(* Logix 5000 project; controller LinePLC1 vendor 1 type 14 code 154 rev 32.11; software revision 32.03; part 3 of 3 *)

ADD_ON_INSTRUCTION FC_Check8Bits   (* revision 1.0, vendor INTRALOX *)
// Check 8 Bits
VAR_INPUT
   b0 : BOOL;   // Input bit 0
   b1 : BOOL;   // Input bit 1
   b2 : BOOL;   // Input bit 2
   b3 : BOOL;   // Input bit 3
   b4 : BOOL;   // Input bit 4
   b5 : BOOL;   // Input bit 5
   b6 : BOOL;   // Input bit 6
   b7 : BOOL;   // Input bit 7
END_VAR
VAR_OUTPUT
   Check8Bits : BOOL;   // Check 8 bits
END_VAR
VAR
   Mem : INT; {access None}
END_VAR

ROUTINE Logic   (* structured text *)
// Check 8 Bits
   // Input bits into mem.
   Mem.0 := b0;
   Mem.1 := b1;
   Mem.2 := b2;
   Mem.3 := b3;
   Mem.4 := b4;
   Mem.5 := b5;
   Mem.6 := b6;
   Mem.7 := b7;
   
   // Make double sure to drop the first byte.
   Mem := Mem AND 16#00FF;
   
   // Check if multiple bits are set.
   IF (Mem AND Mem * -1) = Mem THEN
       Check8Bits := 1;
   ELSE
       Check8Bits := 0;
   END_IF;
   
END_ROUTINE
END_ADD_ON_INSTRUCTION

ADD_ON_INSTRUCTION FC_CheckMultipleBits   (* revision 1.0, vendor INTRALOX *)
// Check Multiple Bits
VAR_INPUT
   Input : INT;
END_VAR
VAR_OUTPUT
   CheckMultipleBits : BOOL; {access Read Only}
END_VAR

ROUTINE Logic   (* structured text *)
// Check Multiple Bits
   // Check if multiple bits are set.
   IF (Input AND Input * -1) = Input THEN
       CheckMultipleBits := 1;
   ELSE
       CheckMultipleBits := 0;
   END_IF;
   
END_ROUTINE
END_ADD_ON_INSTRUCTION

VAR_GLOBAL   (* controller tags *)
   DB_Constants : dt_Constant := (ParameterNr := 4, RecipeNr := 14); {constant, access None}
   DB_General_HMI : dt_General_HMI := (GeneralAlarmBtnCol := 1, AlarmBtnCol := 1); {access None}
   DB_Global : dt_Global; {access None}
   DB_M001_Comms : dt_ISC_CAM_Comm := (DataIn[0] := 23, DataIn[1] := 65535, DataIn[3] := 1, DataIn[4] := 3, DataIn[5] := 8, DataIn[6] := 616, DataIn[7] := 134, DataIn[10] := 60, DataIn[17] := 482, DataIn[19] := 9384, DataIn[21] := 690, DataIn[27] := 4487, DataIn[29] := 9, DataIn[31] := 4, DataIn[32] := 7737, DataIn[33] := 38, DataIn[34] := 616, DataIn[35] := 566, TempDataIn.W1 := 23, TempDataIn.W2 := 65535, TempDataIn.W4 := 1, TempDataIn.W5 := 3, TempDataIn.W6 := 8, TempDataIn.W7 := 616, TempDataIn.W8 := 134, TempDataIn.W11 := 60, TempDataIn.W18 := 482, TempDataIn.W20 := 9384, TempDataIn.W22 := 690, TempDataIn.W28 := 4487, TempDataIn.W30 := 9, TempDataIn.W32 := 4, TempDataIn.W33 := 7737, TempDataIn.W34 := 38, TempDataIn.W35 := 616, TempDataIn.W36 := 566, DataOut[0] := 3, DataOut[1] := 1, DataOut[7] := 1, TempDataOut.W1 := 3, TempDataOut.W2 := 1, TempDataOut.W8 := 1, CommHealthy := 1, CommStatus := 4, ConnectionStatus := 16384, Alarms.iCommsHealthy := 1, tempIn[0] := -581500805, tempIn[1] := 350281047, tempIn[2] := -290188064, tempIn[3] := -1950159180, tempIn[4] := 2984898, tempIn[5] := -515899347, tempIn[6] := 1077600576, tempIn[7] := 868410, tempIn[8] := 13, tempIn[47] := 1966080); {access None}
   DB_M001_HMI : dt_ISCCAM_HMI; {access None}
        .MaintenanceCounters.Counters[0]   // Belt run time - belt elongation.
        .MaintenanceCounters.Counters[1]   // Belt run time - belt contaminants.
        .MaintenanceCounters.Counters[2]   // Belt run time - wearstrip thickness.
        .MaintenanceCounters.Counters[3]   // Belt run time - helix rollers.
        .MaintenanceCounters.Counters[4]   // Belt run time - transfer rollers.
        .MaintenanceCounters.Counters[5]   // Belt run time - return rollers.
        .MaintenanceCounters.Counters[6]   // Belt run time - oil level drive motor.
        .MaintenanceCounters.Counters[7]   // Belt run time - cylinder movement, wear and contaminants, zone 0
        .MaintenanceCounters.Counters[8]   // Belt run time - cylinder movement, wear and contaminants, zone 1
        .MaintenanceCounters.Counters[9]   // Belt run time - cylinder movement, wear and contaminants, zone 2
        .MaintenanceCounters.Counters[10]   // Belt run time - pneumatic system check.
        .MaintenanceCounters.Counters[11]   // Spare
        .MaintenanceCounters.Counters[12]   // Spare
        .MaintenanceCounters.Counters[13]   // Spare
        .MaintenanceCounters.Counters[14]   // Spare
        .MaintenanceCounters.Counters[15]   // Spare
   DB_M001_ISC_CAM_Status : dt_ISC_CAM_Status := (Status.SystemReady := 1, Status.Error := 1, Status.FaultCode.FaultCode24 := 1, Status.FaultCode.FaultCode25 := 1, Status.FaultCode.FaultCode26 := 1, Status.FaultCode.FaultCode27 := 1, Status.FaultCode.FaultCode28 := 1, Status.FaultCode.FaultCode29 := 1, Status.FaultCode.FaultCode30 := 1, Status.FaultCode.FaultCode31 := 1, Status.FaultCode.FaultCode16 := 1, Status.FaultCode.FaultCode17 := 1, Status.FaultCode.FaultCode18 := 1, Status.FaultCode.FaultCode19 := 1, Status.FaultCode.FaultCode20 := 1, Status.FaultCode.FaultCode21 := 1, Status.FaultCode.FaultCode22 := 1, Status.FaultCode.FaultCode23 := 1, Status.Throughput := 3, Status.BeltSpeed := 8, Status.BeltAcceleration := 616, Status.IOstatus.IOStatus9 := 1, Status.IOstatus.IOStatus15 := 1, Status.UpTime := 60, Command.LifeBit := 1, Command.MotorRunning := 1, Command.AssignDestination := 1, Command.DES_Enable1 := 1, DataCollection.BeltRunTime := 482, DataCollection.BeltTravelDistance := 9384, DataCollection.ActivationCount_Zone_0 := 690, DataCollection.ProductCount := 4487, DataCollection.StartStops := 9, DataCollection.GapToSmallCount := 4, DataCollection.FaultCount := 7737, DataCollection.MaxBeltSpeed := 38, DataCollection.PeakAcceleration := 616, DataCollection.PeakDecceleration := 566); {access None}
   DB_M002_Comms : dt_ISC_CAM_Comm := (DataOut[0] := 7667715, DataOut[1] := 1, DataOut[7] := 1, TempDataOut.W1 := 7667715, TempDataOut.W2 := 1, TempDataOut.W8 := 1, CommStatus := 3, ConnectionStatus := 12288, IOConversion.Input := 1, tempIn[7] := -65518, tempIn[8] := 131072, tempIn[9] := 2359325, tempIn[10] := 131327, tempIn[12] := 140, tempIn[13] := 65581, tempIn[14] := 655360, tempIn[15] := 242417664, tempIn[16] := 1333133314, tempIn[17] := 268500992, tempIn[18] := 220528640, tempIn[20] := -1557135340, tempIn[21] := 16646144, tempIn[23] := 7673841, tempIn[24] := 255, tempIn[31] := -2147483618, tempIn[32] := -2147483616, tempIn[33] := -248024064, tempIn[34] := 8796, tempIn[35] := 2375874, tempIn[36] := 1, tempIn[37] := 32, tempIn[38] := 3, tempOut[7] := -65518, tempOut[8] := 131072, tempOut[9] := 2359325, tempOut[10] := 131327, tempOut[12] := 140, tempOut[13] := 65581, tempOut[14] := 655360, tempOut[15] := 242417664, tempOut[16] := 1333133314, tempOut[17] := 268500992, tempOut[18] := 220528640, tempOut[20] := -1557135340, tempOut[21] := 16646144, tempOut[23] := 7673841, tempOut[24] := 255, tempOut[31] := -2147483618, tempOut[32] := -2147483616, tempOut[33] := -248024064, tempOut[34] := 8796, tempOut[35] := 2375874, tempOut[36] := 1, tempOut[37] := 32, tempOut[38] := 3); {access None}
   DB_M002_HMI : dt_ISCCAM_HMI; {access None}
        .MaintenanceCounters.Counters[0]   // Belt run time - belt elongation.
        .MaintenanceCounters.Counters[1]   // Belt run time - belt contaminants.
        .MaintenanceCounters.Counters[2]   // Belt run time - wearstrip thickness.
        .MaintenanceCounters.Counters[3]   // Belt run time - helix rollers.
        .MaintenanceCounters.Counters[4]   // Belt run time - transfer rollers.
        .MaintenanceCounters.Counters[5]   // Belt run time - return rollers.
        .MaintenanceCounters.Counters[6]   // Belt run time - oil level drive motor.
        .MaintenanceCounters.Counters[7]   // Belt run time - cylinder movement, wear and contaminants, zone 0
        .MaintenanceCounters.Counters[8]   // Belt run time - cylinder movement, wear and contaminants, zone 1
        .MaintenanceCounters.Counters[9]   // Belt run time - cylinder movement, wear and contaminants, zone 2
        .MaintenanceCounters.Counters[10]   // Belt run time - pneumatic system check.
        .MaintenanceCounters.Counters[11]   // Spare
        .MaintenanceCounters.Counters[12]   // Spare
        .MaintenanceCounters.Counters[13]   // Spare
        .MaintenanceCounters.Counters[14]   // Spare
        .MaintenanceCounters.Counters[15]   // Spare
   DB_M002_ISC_CAM_Status : dt_ISC_CAM_Status := (Status.FaultCode.FaultCode8 := 1, Status.FaultCode.FaultCode9 := 1, Status.FaultCode.FaultCode10 := 1, Status.FaultCode.FaultCode11 := 1, Status.FaultCode.FaultCode12 := 1, Status.FaultCode.FaultCode13 := 1, Status.FaultCode.FaultCode14 := 1, Status.FaultCode.FaultCode15 := 1, Status.FaultCode.FaultCode0 := 1, Status.FaultCode.FaultCode1 := 1, Status.FaultCode.FaultCode2 := 1, Status.FaultCode.FaultCode3 := 1, Status.FaultCode.FaultCode4 := 1, Status.FaultCode.FaultCode5 := 1, Status.FaultCode.FaultCode6 := 1, Status.FaultCode.FaultCode7 := 1, Status.FaultCode.FaultCode24 := 1, Status.FaultCode.FaultCode25 := 1, Status.FaultCode.FaultCode26 := 1, Status.FaultCode.FaultCode27 := 1, Status.FaultCode.FaultCode28 := 1, Status.FaultCode.FaultCode29 := 1, Status.FaultCode.FaultCode30 := 1, Status.FaultCode.FaultCode31 := 1, Status.FaultCode.FaultCode16 := 1, Status.FaultCode.FaultCode17 := 1, Status.FaultCode.FaultCode18 := 1, Status.FaultCode.FaultCode19 := 1, Status.FaultCode.FaultCode20 := 1, Status.FaultCode.FaultCode21 := 1, Status.FaultCode.FaultCode22 := 1, Status.FaultCode.FaultCode23 := 1, Status.Alarms.CommsAlarm := 1, Status.Alarms.Fault8Alarm := 1, Status.Alarms.Fault9Alarm := 1, Status.Alarms.Fault10Alarm := 1, Status.Alarms.Fault11Alarm := 1, Status.Alarms.Fault12Alarm := 1, Status.Alarms.Fault13Alarm := 1, Status.Alarms.Fault14Alarm := 1, Status.Alarms.Fault15Alarm := 1, Status.Alarms.Fault0Alarm := 1, Status.Alarms.Fault1Alarm := 1, Status.Alarms.Fault2Alarm := 1, Status.Alarms.Fault3Alarm := 1, Status.Alarms.Fault4Alarm := 1, Status.Alarms.Fault5Alarm := 1, Status.Alarms.Fault6Alarm := 1, Status.Alarms.Fault7Alarm := 1, Command.LifeBit := 1, Command.MotorRunning := 1, Command.AssignDestination := 1, Command.DES_Enable1 := 1); {access None}
   DB_Maintenance_M001 : dt_ISC_CAM_Maintenance := (Maintenance[0].iCounter := 482, Maintenance[1].iCounter := 482, Maintenance[2].iCounter := 482, Maintenance[3].iCounter := 482, Maintenance[4].iCounter := 482, Maintenance[5].iCounter := 482, Maintenance[6].iCounter := 482, Maintenance[7].iCounter := 482, Maintenance[8].iCounter := 482, Maintenance[9].iCounter := 482, Maintenance[10].iCounter := 482); {access None}
        .Maintenance[14]   // Spare
        .Maintenance[12]   // Spare
        .Maintenance[13]   // Spare
        .Maintenance[15]   // Spare
        .Maintenance[0]   // Belt run time - belt elongation.
        .Maintenance[1]   // Belt run time - belt contaminants.
        .Maintenance[2]   // Belt run time - wearstrip thickness.
        .Maintenance[3]   // Belt run time - helix rollers.
        .Maintenance[4]   // Belt run time - transfer rollers.
        .Maintenance[5]   // Belt run time - return rollers.
        .Maintenance[6]   // Belt run time - oil level drive motor.
        .Maintenance[10]   // Belt run time - pneumatic system check.
        .Maintenance[11]   // Spare
        .Maintenance[7]   // Belt run time - cylinder movement, wear and contaminants, zone 0
        .Maintenance[8]   // Belt run time - cylinder movement, wear and contaminants, zone 1
        .Maintenance[9]   // Belt run time - cylinder movement, wear and contaminants, zone 2
   DB_Maintenance_M002 : dt_ISC_CAM_Maintenance := (Maintenance[0].iCounter := 16717809, Maintenance[1].iCounter := 16717809, Maintenance[2].iCounter := 16717809, Maintenance[3].iCounter := 16717809, Maintenance[4].iCounter := 16717809, Maintenance[5].iCounter := 16717809, Maintenance[6].iCounter := 16717809, Maintenance[7].iCounter := 16717809, Maintenance[8].iCounter := 16717809, Maintenance[9].iCounter := 16717809, Maintenance[10].iCounter := 16717809); {access None}
        .Maintenance[15]   // Spare
        .Maintenance[0]   // Belt run time - belt elongation.
        .Maintenance[1]   // Belt run time - belt contaminants.
        .Maintenance[2]   // Belt run time - wearstrip thickness.
        .Maintenance[3]   // Belt run time - helix rollers.
        .Maintenance[4]   // Belt run time - transfer rollers.
        .Maintenance[5]   // Belt run time - return rollers.
        .Maintenance[6]   // Belt run time - oil level drive motor.
        .Maintenance[10]   // Belt run time - pneumatic system check.
        .Maintenance[11]   // Spare
        .Maintenance[12]   // Spare
        .Maintenance[13]   // Spare
        .Maintenance[14]   // Spare
        .Maintenance[7]   // Belt run time - cylinder movement, wear and contaminants, zone 0
        .Maintenance[8]   // Belt run time - cylinder movement, wear and contaminants, zone 1
        .Maintenance[9]   // Belt run time - cylinder movement, wear and contaminants, zone 2
END_VAR

PROGRAM MainProgram   (* main routine MainRoutine *)
VAR
   FaultCount_M001 : DINT; {access None}
   FaultCount_M002 : DINT := 131071; {access None}
   fGO_Timer_00_M001 : FBD_TIMER := (PRE := 3000); {access None}
   fGO_Timer_00_M002 : FBD_TIMER := (TimerEnable := 1, PRE := 3000); {access None}
   fGO_Timer_01_M001 : FBD_TIMER := (PRE := 3000); {access None}
   fGO_Timer_01_M002 : FBD_TIMER := (PRE := 3000); {access None}
   i : SINT; {access None}
   iDB_Generl_Diagnostics : DINT; {access None}
END_VAR

ROUTINE General_Diagnostics   (* ladder *)
// General_Diagnostics
   // Add check routines for remote IO to be available / reacheable on th EIP network.
   // Done through msg instructions
   0: NOP();
END_ROUTINE

ROUTINE General_Faults   (* structured text *)
// General Faults
   // Collection of all fault bits.
   
   // General fault indicator.
   DB_General_HMI.GeneralFault := DB_General_HMI.GeneralFaultGroupBits <> 0;
   
END_ROUTINE

ROUTINE General_HMI   (* structured text *)
// General HMI
   // General HMI
   
   // Main alarm button color.
   // Fault color.
   IF DB_General_HMI.GeneralFault OR
       DB_M001_HMI.Fault OR
       DB_M002_HMI.Fault THEN
       DB_General_HMI.GeneralAlarmBtnCol := 1;
   // Maintenance color.
   ELSIF
       DB_M001_HMI.MaintenanceCounters.Counters[0].WarningBit OR DB_M001_HMI.MaintenanceCounters.Counters[1].WarningBit OR
       DB_M002_HMI.MaintenanceCounters.Counters[0].WarningBit OR DB_M002_HMI.MaintenanceCounters.Counters[1].WarningBit THEN
       DB_General_HMI.GeneralAlarmBtnCol := 3;
   // No color.
   ELSE
       DB_General_HMI.GeneralAlarmBtnCol := 0;
   END_IF;
   //;
   
   
   // Reset button.
   DB_General_HMI.GeneralResetBtnCmd := DB_General_HMI.GeneralResetBtnCmd; // Dummie
   //;
   
   
   // Alarm button color.
   // Fault color.
   IF DB_General_HMI.GeneralFault OR
       DB_M001_HMI.Fault OR
       DB_M002_HMI.Fault THEN
       DB_General_HMI.AlarmBtnCol := 1;
   // No color.
   ELSE
       DB_General_HMI.AlarmBtnCol := 0;
   END_IF;
   //;
   
   
   // Maintenance button color.
   // Fault color.
   IF DB_M001_HMI.MaintenanceCounters.Counters[0].WarningBit OR DB_M001_HMI.MaintenanceCounters.Counters[1].WarningBit OR
       DB_M002_HMI.MaintenanceCounters.Counters[0].WarningBit  OR DB_M002_HMI.MaintenanceCounters.Counters[1].WarningBit THEN
       DB_General_HMI.MaintenanceBtnCol := 3;
   // No color.
   ELSE
       DB_General_HMI.MaintenanceBtnCol := 0;
   END_IF;
   //;
   
   
END_ROUTINE

ROUTINE M001_Faults   (* structured text *)
   //Fault group 0, ISC device state errors.
   //Group reset
   If(DB_General_HMI.GeneralResetBtnCmd) Then
   	DB_M001_HMI.FaultBits.CommsAlarm := 0;
   	DB_M001_HMI.FaultBits.Fault0Alarm := 0;
   	DB_M001_HMI.FaultBits.Fault1Alarm := 0;
   	DB_M001_HMI.FaultBits.Fault2Alarm := 0;
   	DB_M001_HMI.FaultBits.Fault3Alarm := 0;
   	DB_M001_HMI.FaultBits.Fault4Alarm := 0;
   	DB_M001_HMI.FaultBits.Fault5Alarm := 0;
   	DB_M001_HMI.FaultBits.Fault6Alarm := 0;
   	DB_M001_HMI.FaultBits.Fault7Alarm := 0;
   	DB_M001_HMI.FaultBits.Fault8Alarm := 0;
   	DB_M001_HMI.FaultBits.Fault9Alarm := 0;
   	DB_M001_HMI.FaultBits.Fault10Alarm := 0;
   	DB_M001_HMI.FaultBits.Fault11Alarm := 0;
   	DB_M001_HMI.FaultBits.Fault12Alarm := 0;
   	DB_M001_HMI.FaultBits.Fault13Alarm := 0;
   	DB_M001_HMI.FaultBits.Fault14Alarm := 0;
   	DB_M001_HMI.FaultBits.Fault15Alarm := 0;
   end_if;
   
   
   //Lifebit error
   TONR(fGO_Timer_00_M001);
   fGO_Timer_00_M001.PRE := 3000;
   fGO_Timer_00_M001.TimerEnable := NOT DB_M001_ISC_CAM_Status.Status.LifeBit;
   
   TONR(fGO_Timer_01_M001);
   fGO_Timer_01_M001.PRE := 3000;
   fGO_Timer_01_M001.TimerEnable := DB_M001_ISC_CAM_Status.Status.LifeBit;
   
   
   If(NOT DB_M001_HMI.FaultBits.CommsAlarm  AND (fGO_Timer_00_M001.DN OR fGO_Timer_01_M001.DN)) then
   	DB_M001_HMI.FaultBits.CommsAlarm := 1;
   end_if;
   
   If(NOT DB_M001_HMI.FaultBits.Fault0Alarm  AND DB_M001_ISC_CAM_Status.Status.Alarms.Fault0Alarm) then
   	DB_M001_HMI.FaultBits.Fault0Alarm := 1;
   end_if;
   
   If(NOT DB_M001_HMI.FaultBits.Fault1Alarm  AND DB_M001_ISC_CAM_Status.Status.Alarms.Fault1Alarm) then
   	DB_M001_HMI.FaultBits.Fault1Alarm := 1;
   end_if;
   
   If(NOT DB_M001_HMI.FaultBits.Fault2Alarm  AND DB_M001_ISC_CAM_Status.Status.Alarms.Fault2Alarm) then
   	DB_M001_HMI.FaultBits.Fault2Alarm := 1;
   end_if;
   
   If(NOT DB_M001_HMI.FaultBits.Fault3Alarm  AND DB_M001_ISC_CAM_Status.Status.Alarms.Fault3Alarm) then
   	DB_M001_HMI.FaultBits.Fault3Alarm := 1;
   end_if;
   
   If(NOT DB_M001_HMI.FaultBits.Fault4Alarm  AND DB_M001_ISC_CAM_Status.Status.Alarms.Fault4Alarm) then
   	DB_M001_HMI.FaultBits.Fault4Alarm := 1;
   end_if;
   
   If(NOT DB_M001_HMI.FaultBits.Fault5Alarm  AND DB_M001_ISC_CAM_Status.Status.Alarms.Fault5Alarm) then
   	DB_M001_HMI.FaultBits.Fault5Alarm := 1;
   end_if;
   
   If(NOT DB_M001_HMI.FaultBits.Fault6Alarm  AND DB_M001_ISC_CAM_Status.Status.Alarms.Fault6Alarm) then
   	DB_M001_HMI.FaultBits.Fault6Alarm := 1;
   end_if;
   
   If(NOT DB_M001_HMI.FaultBits.Fault7Alarm  AND DB_M001_ISC_CAM_Status.Status.Alarms.Fault7Alarm) then
   	DB_M001_HMI.FaultBits.Fault7Alarm := 1;
   end_if;
   
   If(NOT DB_M001_HMI.FaultBits.Fault8Alarm  AND DB_M001_ISC_CAM_Status.Status.Alarms.Fault8Alarm) then
   	DB_M001_HMI.FaultBits.Fault8Alarm := 1;
   end_if;
   
   If(NOT DB_M001_HMI.FaultBits.Fault9Alarm  AND DB_M001_ISC_CAM_Status.Status.Alarms.Fault9Alarm) then
   	DB_M001_HMI.FaultBits.Fault9Alarm := 1;
   end_if;
   
   If(NOT DB_M001_HMI.FaultBits.Fault10Alarm  AND DB_M001_ISC_CAM_Status.Status.Alarms.Fault10Alarm) then
   	DB_M001_HMI.FaultBits.Fault10Alarm := 1;
   end_if;
   
   If(NOT DB_M001_HMI.FaultBits.Fault11Alarm  AND DB_M001_ISC_CAM_Status.Status.Alarms.Fault11Alarm) then
   	DB_M001_HMI.FaultBits.Fault11Alarm := 1;
   end_if;
   
   If(NOT DB_M001_HMI.FaultBits.Fault12Alarm  AND DB_M001_ISC_CAM_Status.Status.Alarms.Fault12Alarm) then
   	DB_M001_HMI.FaultBits.Fault12Alarm := 1;
   end_if;
   
   If(NOT DB_M001_HMI.FaultBits.Fault13Alarm  AND DB_M001_ISC_CAM_Status.Status.Alarms.Fault13Alarm) then
   	DB_M001_HMI.FaultBits.Fault13Alarm := 1;
   end_if;
   
   If(NOT DB_M001_HMI.FaultBits.Fault14Alarm  AND DB_M001_ISC_CAM_Status.Status.Alarms.Fault14Alarm) then
   	DB_M001_HMI.FaultBits.Fault14Alarm := 1;
   end_if;
   
   If(NOT DB_M001_HMI.FaultBits.Fault15Alarm  AND DB_M001_ISC_CAM_Status.Status.Alarms.Fault15Alarm) then
   	DB_M001_HMI.FaultBits.Fault15Alarm := 1;
   end_if;
   
   //Fault count
   COP(DB_M001_HMI.FaultBits, FaultCount_M001, 16);
   
   If(FaultCount_M001>0 AND NOT DB_M001_HMI.Fault) then
   	DB_M001_HMI.Fault := 1;
   elsif FaultCount_M001=0 AND DB_M001_HMI.Fault Then
   	DB_M001_HMI.Fault := 0;
   end_if;
END_ROUTINE

ROUTINE M001_Main   (* ladder *)
// M001 Main
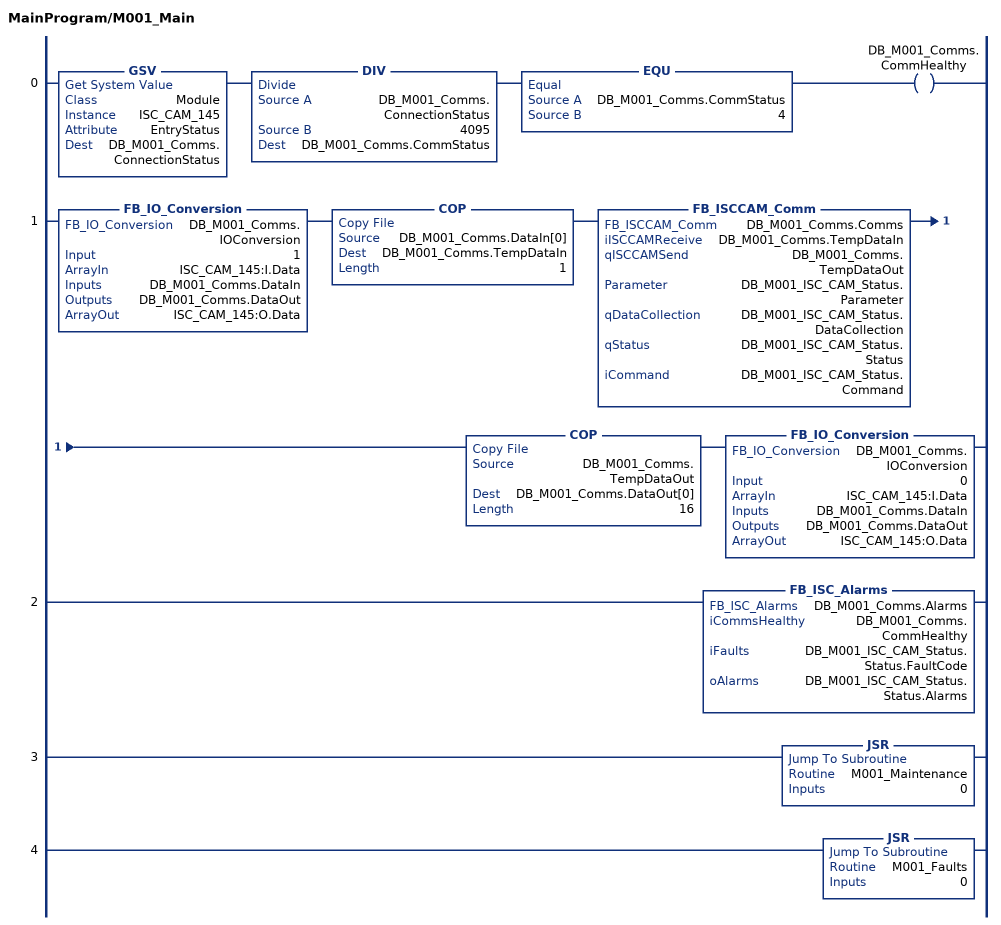
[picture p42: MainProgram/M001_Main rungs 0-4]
   0: GSV(Module,ISC_CAM_145,EntryStatus,DB_M001_Comms.ConnectionStatus)DIV(DB_M001_Comms.ConnectionStatus,4095,DB_M001_Comms.CommStatus)EQU(DB_M001_Comms.CommStatus,4)OTE(DB_M001_Comms.CommHealthy);
   1: FB_IO_Conversion(DB_M001_Comms.IOConversion,1,ISC_CAM_145:I.Data,DB_M001_Comms.DataIn,DB_M001_Comms.DataOut,ISC_CAM_145:O.Data)COP(DB_M001_Comms.DataIn[0],DB_M001_Comms.TempDataIn,1)FB_ISCCAM_Comm(DB_M001_Comms.Comms,DB_M001_Comms.TempDataIn,DB_M001_Comms.TempDataOut,DB_M001_ISC_CAM_Status.Parameter,DB_M001_ISC_CAM_Status.DataCollection,DB_M001_ISC_CAM_Status.Status,DB_M001_ISC_CAM_Status.Command)COP(DB_M001_Comms.TempDataOut,DB_M001_Comms.DataOut[0],16)FB_IO_Conversion(DB_M001_Comms.IOConversion,0,ISC_CAM_145:I.Data,DB_M001_Comms.DataIn,DB_M001_Comms.DataOut,ISC_CAM_145:O.Data);
   2: FB_ISC_Alarms(DB_M001_Comms.Alarms,DB_M001_Comms.CommHealthy,DB_M001_ISC_CAM_Status.Status.FaultCode,DB_M001_ISC_CAM_Status.Status.Alarms);
   3: JSR(M001_Maintenance,0);
   4: JSR(M001_Faults,0);
END_ROUTINE

ROUTINE M001_Maintenance   (* ladder *)
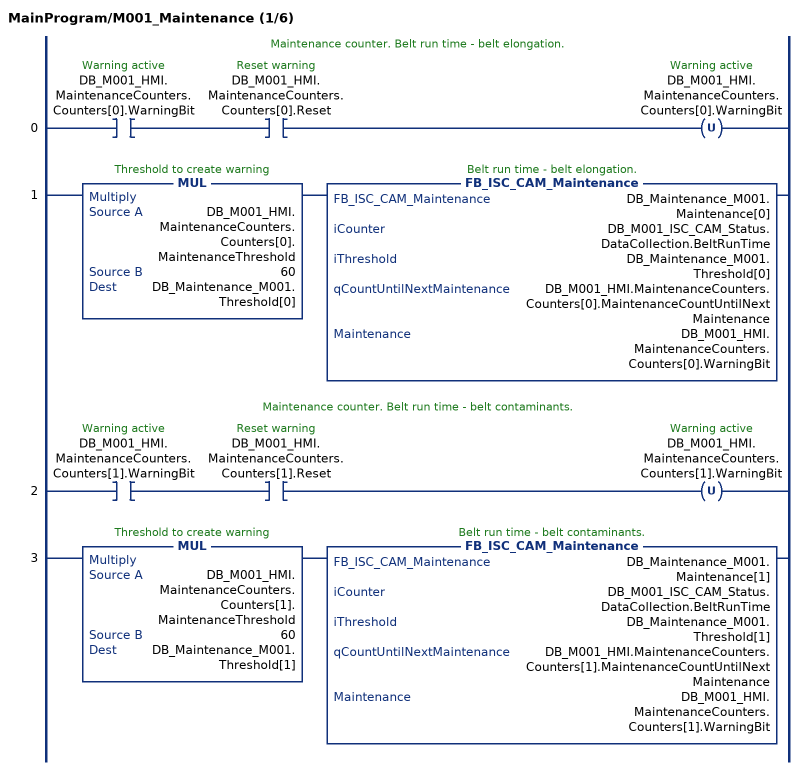
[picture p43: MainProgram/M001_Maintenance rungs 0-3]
   // Maintenance counter. Belt run time - belt elongation.
   0: XIC(DB_M001_HMI.MaintenanceCounters.Counters[0].WarningBit)XIC(DB_M001_HMI.MaintenanceCounters.Counters[0].Reset)OTU(DB_M001_HMI.MaintenanceCounters.Counters[0].WarningBit);
   1: MUL(DB_M001_HMI.MaintenanceCounters.Counters[0].MaintenanceThreshold,60,DB_Maintenance_M001.Threshold[0])FB_ISC_CAM_Maintenance(DB_Maintenance_M001.Maintenance[0],DB_M001_ISC_CAM_Status.DataCollection.BeltRunTime,DB_Maintenance_M001.Threshold[0],DB_M001_HMI.MaintenanceCounters.Counters[0].MaintenanceCountUntilNextMaintenance,DB_M001_HMI.MaintenanceCounters.Counters[0].WarningBit);
   // Maintenance counter. Belt run time - belt contaminants.
   2: XIC(DB_M001_HMI.MaintenanceCounters.Counters[1].WarningBit)XIC(DB_M001_HMI.MaintenanceCounters.Counters[1].Reset)OTU(DB_M001_HMI.MaintenanceCounters.Counters[1].WarningBit);
   3: MUL(DB_M001_HMI.MaintenanceCounters.Counters[1].MaintenanceThreshold,60,DB_Maintenance_M001.Threshold[1])FB_ISC_CAM_Maintenance(DB_Maintenance_M001.Maintenance[1],DB_M001_ISC_CAM_Status.DataCollection.BeltRunTime,DB_Maintenance_M001.Threshold[1],DB_M001_HMI.MaintenanceCounters.Counters[1].MaintenanceCountUntilNextMaintenance,DB_M001_HMI.MaintenanceCounters.Counters[1].WarningBit);
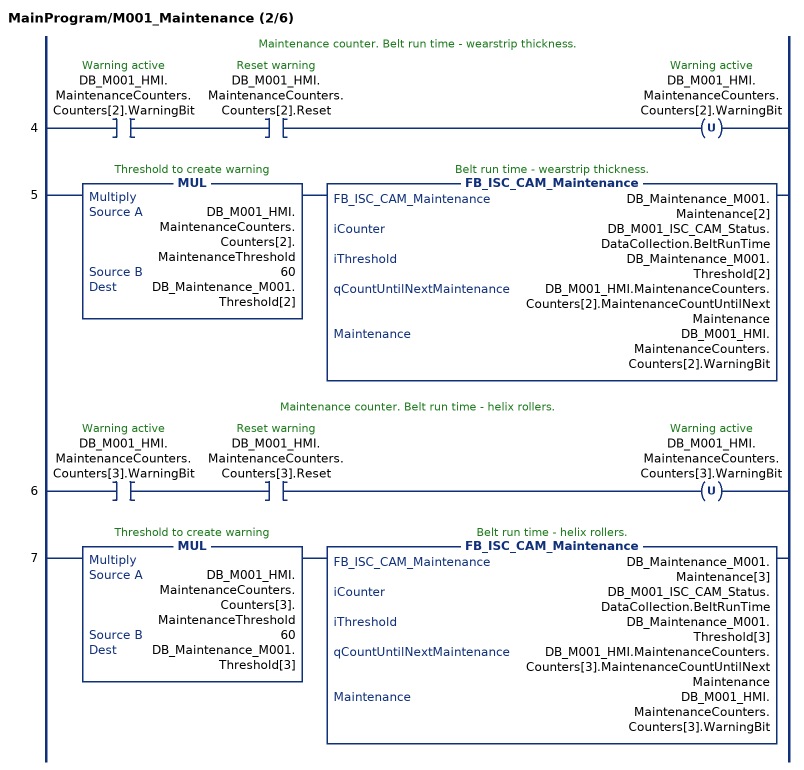
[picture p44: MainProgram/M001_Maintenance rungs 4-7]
   // Maintenance counter. Belt run time - wearstrip thickness.
   4: XIC(DB_M001_HMI.MaintenanceCounters.Counters[2].WarningBit)XIC(DB_M001_HMI.MaintenanceCounters.Counters[2].Reset)OTU(DB_M001_HMI.MaintenanceCounters.Counters[2].WarningBit);
   5: MUL(DB_M001_HMI.MaintenanceCounters.Counters[2].MaintenanceThreshold,60,DB_Maintenance_M001.Threshold[2])FB_ISC_CAM_Maintenance(DB_Maintenance_M001.Maintenance[2],DB_M001_ISC_CAM_Status.DataCollection.BeltRunTime,DB_Maintenance_M001.Threshold[2],DB_M001_HMI.MaintenanceCounters.Counters[2].MaintenanceCountUntilNextMaintenance,DB_M001_HMI.MaintenanceCounters.Counters[2].WarningBit);
   // Maintenance counter. Belt run time - helix rollers.
   6: XIC(DB_M001_HMI.MaintenanceCounters.Counters[3].WarningBit)XIC(DB_M001_HMI.MaintenanceCounters.Counters[3].Reset)OTU(DB_M001_HMI.MaintenanceCounters.Counters[3].WarningBit);
   7: MUL(DB_M001_HMI.MaintenanceCounters.Counters[3].MaintenanceThreshold,60,DB_Maintenance_M001.Threshold[3])FB_ISC_CAM_Maintenance(DB_Maintenance_M001.Maintenance[3],DB_M001_ISC_CAM_Status.DataCollection.BeltRunTime,DB_Maintenance_M001.Threshold[3],DB_M001_HMI.MaintenanceCounters.Counters[3].MaintenanceCountUntilNextMaintenance,DB_M001_HMI.MaintenanceCounters.Counters[3].WarningBit);
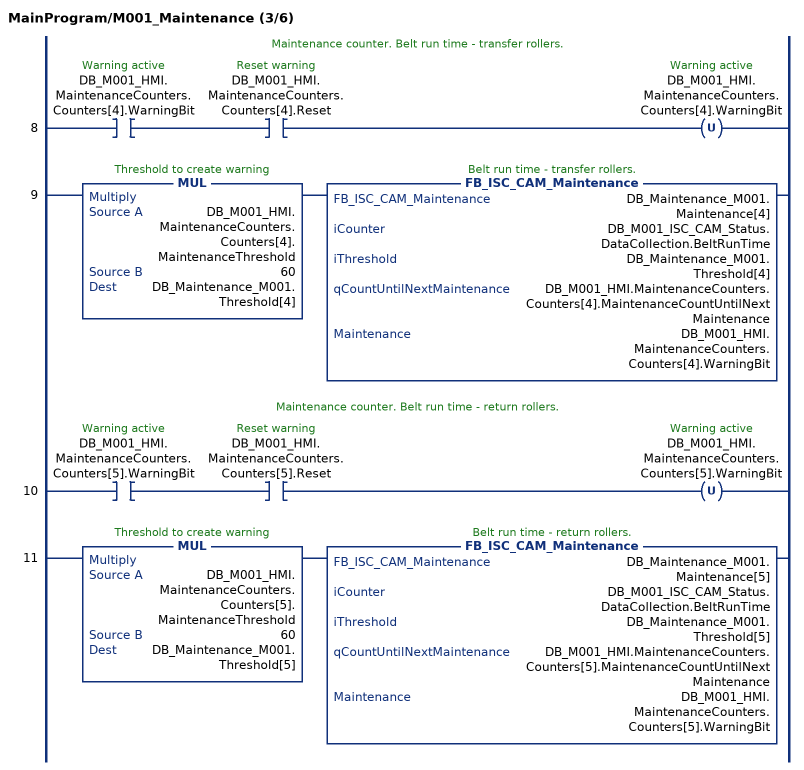
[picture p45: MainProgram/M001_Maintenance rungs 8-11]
   // Maintenance counter. Belt run time - transfer rollers.
   8: XIC(DB_M001_HMI.MaintenanceCounters.Counters[4].WarningBit)XIC(DB_M001_HMI.MaintenanceCounters.Counters[4].Reset)OTU(DB_M001_HMI.MaintenanceCounters.Counters[4].WarningBit);
   9: MUL(DB_M001_HMI.MaintenanceCounters.Counters[4].MaintenanceThreshold,60,DB_Maintenance_M001.Threshold[4])FB_ISC_CAM_Maintenance(DB_Maintenance_M001.Maintenance[4],DB_M001_ISC_CAM_Status.DataCollection.BeltRunTime,DB_Maintenance_M001.Threshold[4],DB_M001_HMI.MaintenanceCounters.Counters[4].MaintenanceCountUntilNextMaintenance,DB_M001_HMI.MaintenanceCounters.Counters[4].WarningBit);
   // Maintenance counter. Belt run time - return rollers.
   10: XIC(DB_M001_HMI.MaintenanceCounters.Counters[5].WarningBit)XIC(DB_M001_HMI.MaintenanceCounters.Counters[5].Reset)OTU(DB_M001_HMI.MaintenanceCounters.Counters[5].WarningBit);
   11: MUL(DB_M001_HMI.MaintenanceCounters.Counters[5].MaintenanceThreshold,60,DB_Maintenance_M001.Threshold[5])FB_ISC_CAM_Maintenance(DB_Maintenance_M001.Maintenance[5],DB_M001_ISC_CAM_Status.DataCollection.BeltRunTime,DB_Maintenance_M001.Threshold[5],DB_M001_HMI.MaintenanceCounters.Counters[5].MaintenanceCountUntilNextMaintenance,DB_M001_HMI.MaintenanceCounters.Counters[5].WarningBit);
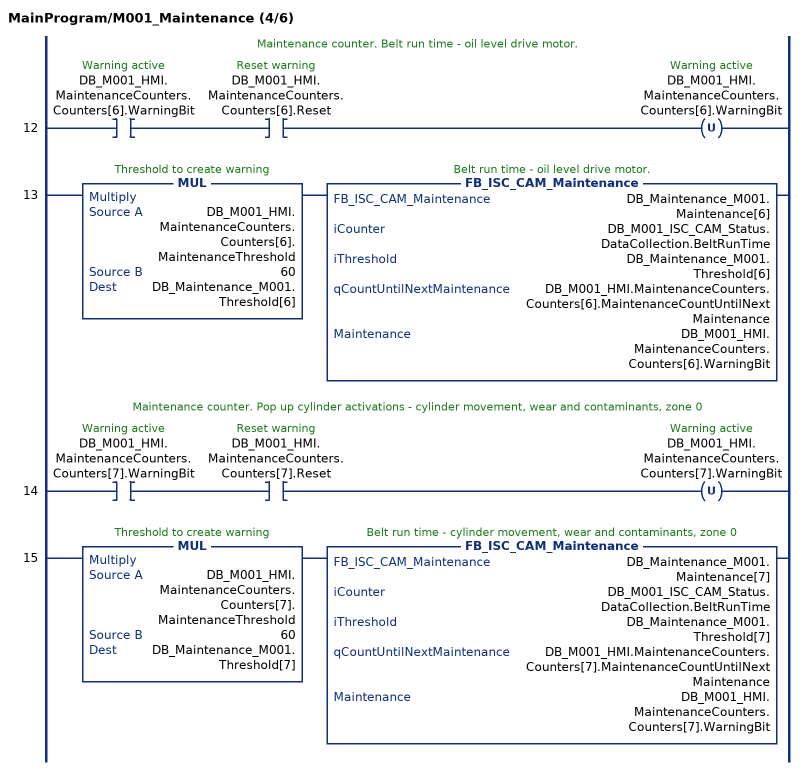
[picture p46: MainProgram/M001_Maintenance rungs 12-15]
   // Maintenance counter. Belt run time - oil level drive motor.
   12: XIC(DB_M001_HMI.MaintenanceCounters.Counters[6].WarningBit)XIC(DB_M001_HMI.MaintenanceCounters.Counters[6].Reset)OTU(DB_M001_HMI.MaintenanceCounters.Counters[6].WarningBit);
   13: MUL(DB_M001_HMI.MaintenanceCounters.Counters[6].MaintenanceThreshold,60,DB_Maintenance_M001.Threshold[6])FB_ISC_CAM_Maintenance(DB_Maintenance_M001.Maintenance[6],DB_M001_ISC_CAM_Status.DataCollection.BeltRunTime,DB_Maintenance_M001.Threshold[6],DB_M001_HMI.MaintenanceCounters.Counters[6].MaintenanceCountUntilNextMaintenance,DB_M001_HMI.MaintenanceCounters.Counters[6].WarningBit);
   // Maintenance counter. Pop up cylinder activations - cylinder movement, wear and contaminants, zone 0
   14: XIC(DB_M001_HMI.MaintenanceCounters.Counters[7].WarningBit)XIC(DB_M001_HMI.MaintenanceCounters.Counters[7].Reset)OTU(DB_M001_HMI.MaintenanceCounters.Counters[7].WarningBit);
   15: MUL(DB_M001_HMI.MaintenanceCounters.Counters[7].MaintenanceThreshold,60,DB_Maintenance_M001.Threshold[7])FB_ISC_CAM_Maintenance(DB_Maintenance_M001.Maintenance[7],DB_M001_ISC_CAM_Status.DataCollection.BeltRunTime,DB_Maintenance_M001.Threshold[7],DB_M001_HMI.MaintenanceCounters.Counters[7].MaintenanceCountUntilNextMaintenance,DB_M001_HMI.MaintenanceCounters.Counters[7].WarningBit);
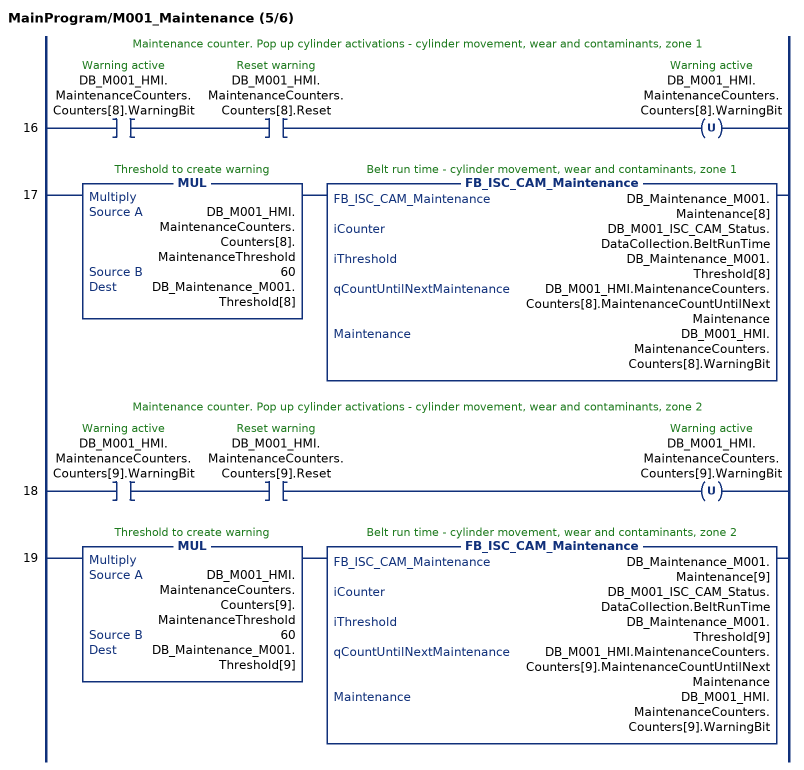
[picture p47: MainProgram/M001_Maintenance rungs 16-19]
   // Maintenance counter. Pop up cylinder activations - cylinder movement, wear and contaminants, zone 1
   16: XIC(DB_M001_HMI.MaintenanceCounters.Counters[8].WarningBit)XIC(DB_M001_HMI.MaintenanceCounters.Counters[8].Reset)OTU(DB_M001_HMI.MaintenanceCounters.Counters[8].WarningBit);
   17: MUL(DB_M001_HMI.MaintenanceCounters.Counters[8].MaintenanceThreshold,60,DB_Maintenance_M001.Threshold[8])FB_ISC_CAM_Maintenance(DB_Maintenance_M001.Maintenance[8],DB_M001_ISC_CAM_Status.DataCollection.BeltRunTime,DB_Maintenance_M001.Threshold[8],DB_M001_HMI.MaintenanceCounters.Counters[8].MaintenanceCountUntilNextMaintenance,DB_M001_HMI.MaintenanceCounters.Counters[8].WarningBit);
   // Maintenance counter. Pop up cylinder activations - cylinder movement, wear and contaminants, zone 2
   18: XIC(DB_M001_HMI.MaintenanceCounters.Counters[9].WarningBit)XIC(DB_M001_HMI.MaintenanceCounters.Counters[9].Reset)OTU(DB_M001_HMI.MaintenanceCounters.Counters[9].WarningBit);
   19: MUL(DB_M001_HMI.MaintenanceCounters.Counters[9].MaintenanceThreshold,60,DB_Maintenance_M001.Threshold[9])FB_ISC_CAM_Maintenance(DB_Maintenance_M001.Maintenance[9],DB_M001_ISC_CAM_Status.DataCollection.BeltRunTime,DB_Maintenance_M001.Threshold[9],DB_M001_HMI.MaintenanceCounters.Counters[9].MaintenanceCountUntilNextMaintenance,DB_M001_HMI.MaintenanceCounters.Counters[9].WarningBit);
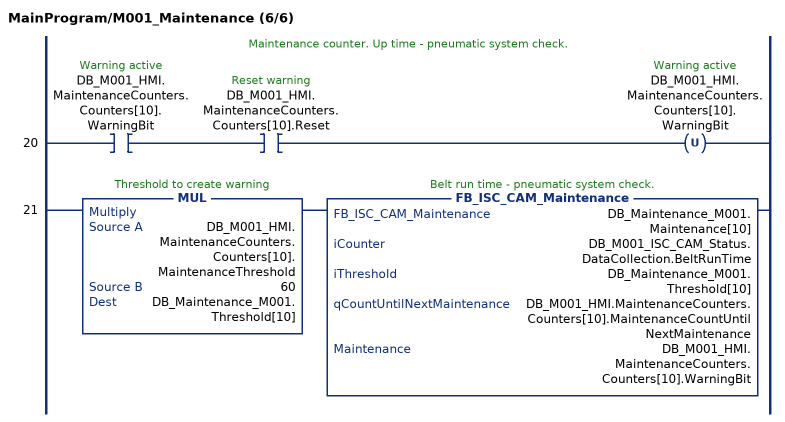
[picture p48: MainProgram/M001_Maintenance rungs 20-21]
   // Maintenance counter. Up time - pneumatic system check.
   20: XIC(DB_M001_HMI.MaintenanceCounters.Counters[10].WarningBit)XIC(DB_M001_HMI.MaintenanceCounters.Counters[10].Reset)OTU(DB_M001_HMI.MaintenanceCounters.Counters[10].WarningBit);
   21: MUL(DB_M001_HMI.MaintenanceCounters.Counters[10].MaintenanceThreshold,60,DB_Maintenance_M001.Threshold[10])FB_ISC_CAM_Maintenance(DB_Maintenance_M001.Maintenance[10],DB_M001_ISC_CAM_Status.DataCollection.BeltRunTime,DB_Maintenance_M001.Threshold[10],DB_M001_HMI.MaintenanceCounters.Counters[10].MaintenanceCountUntilNextMaintenance,DB_M001_HMI.MaintenanceCounters.Counters[10].WarningBit);
END_ROUTINE

ROUTINE M002_Faults   (* structured text *)
   //Fault group 0, ISC device state errors.
   //Group reset
   If(DB_General_HMI.GeneralResetBtnCmd) Then
   	DB_M002_HMI.FaultBits.CommsAlarm := 0;
   	DB_M002_HMI.FaultBits.Fault0Alarm := 0;
   	DB_M002_HMI.FaultBits.Fault1Alarm := 0;
   	DB_M002_HMI.FaultBits.Fault2Alarm := 0;
   	DB_M002_HMI.FaultBits.Fault3Alarm := 0;
   	DB_M002_HMI.FaultBits.Fault4Alarm := 0;
   	DB_M002_HMI.FaultBits.Fault5Alarm := 0;
   	DB_M002_HMI.FaultBits.Fault6Alarm := 0;
   	DB_M002_HMI.FaultBits.Fault7Alarm := 0;
   	DB_M002_HMI.FaultBits.Fault8Alarm := 0;
   	DB_M002_HMI.FaultBits.Fault9Alarm := 0;
   	DB_M002_HMI.FaultBits.Fault10Alarm := 0;
   	DB_M002_HMI.FaultBits.Fault11Alarm := 0;
   	DB_M002_HMI.FaultBits.Fault12Alarm := 0;
   	DB_M002_HMI.FaultBits.Fault13Alarm := 0;
   	DB_M002_HMI.FaultBits.Fault14Alarm := 0;
   	DB_M002_HMI.FaultBits.Fault15Alarm := 0;
   end_if;
   
   
   //Lifebit error
   TONR(fGO_Timer_00_M002);
   fGO_Timer_00_M002.PRE := 3000;
   fGO_Timer_00_M002.TimerEnable := NOT DB_M002_ISC_CAM_Status.Status.LifeBit;
   
   TONR(fGO_Timer_01_M002);
   fGO_Timer_01_M002.PRE := 3000;
   fGO_Timer_01_M002.TimerEnable := DB_M002_ISC_CAM_Status.Status.LifeBit;
   
   
   If(NOT DB_M002_HMI.FaultBits.CommsAlarm  AND (fGO_Timer_00_M002.DN OR fGO_Timer_01_M002.DN)) then
   	DB_M002_HMI.FaultBits.CommsAlarm := 1;
   end_if;
   
   If(NOT DB_M002_HMI.FaultBits.Fault0Alarm  AND DB_M002_ISC_CAM_Status.Status.Alarms.Fault0Alarm) then
   	DB_M002_HMI.FaultBits.Fault0Alarm := 1;
   end_if;
   
   If(NOT DB_M002_HMI.FaultBits.Fault1Alarm  AND DB_M002_ISC_CAM_Status.Status.Alarms.Fault1Alarm) then
   	DB_M002_HMI.FaultBits.Fault1Alarm := 1;
   end_if;
   
   If(NOT DB_M002_HMI.FaultBits.Fault2Alarm  AND DB_M002_ISC_CAM_Status.Status.Alarms.Fault2Alarm) then
   	DB_M002_HMI.FaultBits.Fault2Alarm := 1;
   end_if;
   
   If(NOT DB_M002_HMI.FaultBits.Fault3Alarm  AND DB_M002_ISC_CAM_Status.Status.Alarms.Fault3Alarm) then
   	DB_M002_HMI.FaultBits.Fault3Alarm := 1;
   end_if;
   
   If(NOT DB_M002_HMI.FaultBits.Fault4Alarm  AND DB_M002_ISC_CAM_Status.Status.Alarms.Fault4Alarm) then
   	DB_M002_HMI.FaultBits.Fault4Alarm := 1;
   end_if;
   
   If(NOT DB_M002_HMI.FaultBits.Fault5Alarm  AND DB_M002_ISC_CAM_Status.Status.Alarms.Fault5Alarm) then
   	DB_M002_HMI.FaultBits.Fault5Alarm := 1;
   end_if;
   
   If(NOT DB_M002_HMI.FaultBits.Fault6Alarm  AND DB_M002_ISC_CAM_Status.Status.Alarms.Fault6Alarm) then
   	DB_M002_HMI.FaultBits.Fault6Alarm := 1;
   end_if;
   
   If(NOT DB_M002_HMI.FaultBits.Fault7Alarm  AND DB_M002_ISC_CAM_Status.Status.Alarms.Fault7Alarm) then
   	DB_M002_HMI.FaultBits.Fault7Alarm := 1;
   end_if;
   
   If(NOT DB_M002_HMI.FaultBits.Fault8Alarm  AND DB_M002_ISC_CAM_Status.Status.Alarms.Fault8Alarm) then
   	DB_M002_HMI.FaultBits.Fault8Alarm := 1;
   end_if;
   
   If(NOT DB_M002_HMI.FaultBits.Fault9Alarm  AND DB_M002_ISC_CAM_Status.Status.Alarms.Fault9Alarm) then
   	DB_M002_HMI.FaultBits.Fault9Alarm := 1;
   end_if;
   
   If(NOT DB_M002_HMI.FaultBits.Fault10Alarm  AND DB_M002_ISC_CAM_Status.Status.Alarms.Fault10Alarm) then
   	DB_M002_HMI.FaultBits.Fault10Alarm := 1;
   end_if;
   
   If(NOT DB_M002_HMI.FaultBits.Fault11Alarm  AND DB_M002_ISC_CAM_Status.Status.Alarms.Fault11Alarm) then
   	DB_M002_HMI.FaultBits.Fault11Alarm := 1;
   end_if;
   
   If(NOT DB_M002_HMI.FaultBits.Fault12Alarm  AND DB_M002_ISC_CAM_Status.Status.Alarms.Fault12Alarm) then
   	DB_M002_HMI.FaultBits.Fault12Alarm := 1;
   end_if;
   
   If(NOT DB_M002_HMI.FaultBits.Fault13Alarm  AND DB_M002_ISC_CAM_Status.Status.Alarms.Fault13Alarm) then
   	DB_M002_HMI.FaultBits.Fault13Alarm := 1;
   end_if;
   
   If(NOT DB_M002_HMI.FaultBits.Fault14Alarm  AND DB_M002_ISC_CAM_Status.Status.Alarms.Fault14Alarm) then
   	DB_M002_HMI.FaultBits.Fault14Alarm := 1;
   end_if;
   
   If(NOT DB_M002_HMI.FaultBits.Fault15Alarm  AND DB_M002_ISC_CAM_Status.Status.Alarms.Fault15Alarm) then
   	DB_M002_HMI.FaultBits.Fault15Alarm := 1;
   end_if;
   
   //Fault count
   COP(DB_M002_HMI.FaultBits, FaultCount_M002, 16);
   
   If(FaultCount_M002>0 AND NOT DB_M002_HMI.Fault) then
   	DB_M002_HMI.Fault := 1;
   elsif FaultCount_M002=0 AND DB_M002_HMI.Fault Then
   	DB_M002_HMI.Fault := 0;
   end_if;
END_ROUTINE

ROUTINE M002_Main   (* ladder *)
// M002 Main
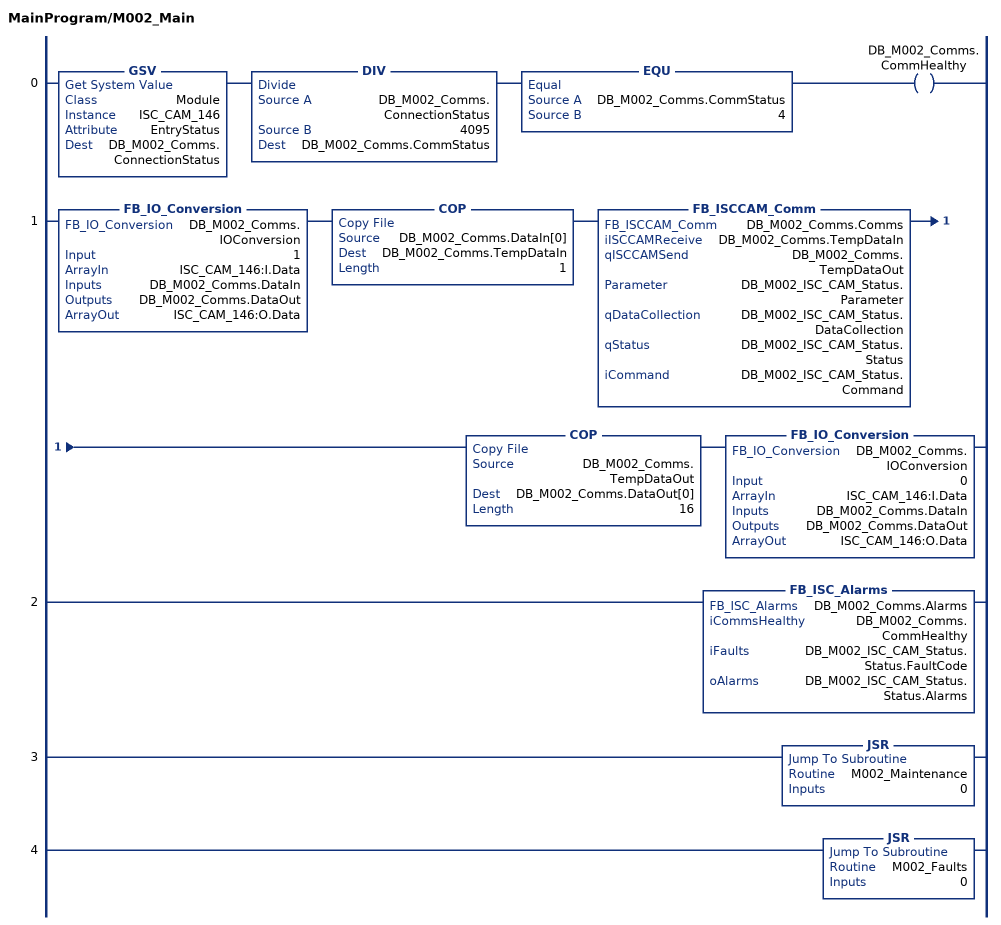
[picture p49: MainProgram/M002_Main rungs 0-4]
   0: GSV(Module,ISC_CAM_146,EntryStatus,DB_M002_Comms.ConnectionStatus)DIV(DB_M002_Comms.ConnectionStatus,4095,DB_M002_Comms.CommStatus)EQU(DB_M002_Comms.CommStatus,4)OTE(DB_M002_Comms.CommHealthy);
   1: FB_IO_Conversion(DB_M002_Comms.IOConversion,1,ISC_CAM_146:I.Data,DB_M002_Comms.DataIn,DB_M002_Comms.DataOut,ISC_CAM_146:O.Data)COP(DB_M002_Comms.DataIn[0],DB_M002_Comms.TempDataIn,1)FB_ISCCAM_Comm(DB_M002_Comms.Comms,DB_M002_Comms.TempDataIn,DB_M002_Comms.TempDataOut,DB_M002_ISC_CAM_Status.Parameter,DB_M002_ISC_CAM_Status.DataCollection,DB_M002_ISC_CAM_Status.Status,DB_M002_ISC_CAM_Status.Command)COP(DB_M002_Comms.TempDataOut,DB_M002_Comms.DataOut[0],16)FB_IO_Conversion(DB_M002_Comms.IOConversion,0,ISC_CAM_146:I.Data,DB_M002_Comms.DataIn,DB_M002_Comms.DataOut,ISC_CAM_146:O.Data);
   2: FB_ISC_Alarms(DB_M002_Comms.Alarms,DB_M002_Comms.CommHealthy,DB_M002_ISC_CAM_Status.Status.FaultCode,DB_M002_ISC_CAM_Status.Status.Alarms);
   3: JSR(M002_Maintenance,0);
   4: JSR(M002_Faults,0);
END_ROUTINE

ROUTINE M002_Maintenance   (* ladder *)
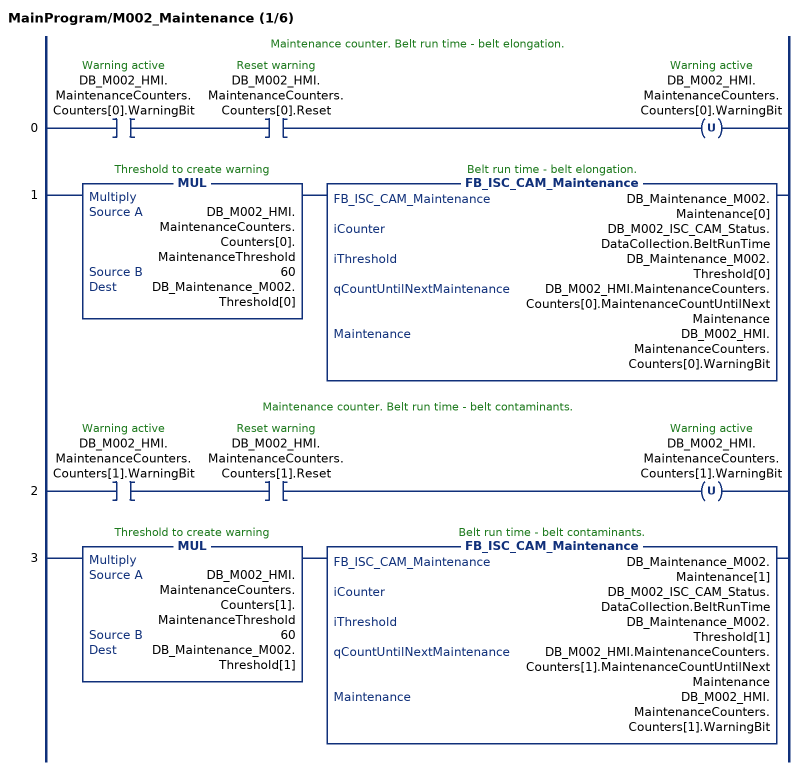
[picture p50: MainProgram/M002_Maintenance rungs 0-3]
   // Maintenance counter. Belt run time - belt elongation.
   0: XIC(DB_M002_HMI.MaintenanceCounters.Counters[0].WarningBit)XIC(DB_M002_HMI.MaintenanceCounters.Counters[0].Reset)OTU(DB_M002_HMI.MaintenanceCounters.Counters[0].WarningBit);
   1: MUL(DB_M002_HMI.MaintenanceCounters.Counters[0].MaintenanceThreshold,60,DB_Maintenance_M002.Threshold[0])FB_ISC_CAM_Maintenance(DB_Maintenance_M002.Maintenance[0],DB_M002_ISC_CAM_Status.DataCollection.BeltRunTime,DB_Maintenance_M002.Threshold[0],DB_M002_HMI.MaintenanceCounters.Counters[0].MaintenanceCountUntilNextMaintenance,DB_M002_HMI.MaintenanceCounters.Counters[0].WarningBit);
   // Maintenance counter. Belt run time - belt contaminants.
   2: XIC(DB_M002_HMI.MaintenanceCounters.Counters[1].WarningBit)XIC(DB_M002_HMI.MaintenanceCounters.Counters[1].Reset)OTU(DB_M002_HMI.MaintenanceCounters.Counters[1].WarningBit);
   3: MUL(DB_M002_HMI.MaintenanceCounters.Counters[1].MaintenanceThreshold,60,DB_Maintenance_M002.Threshold[1])FB_ISC_CAM_Maintenance(DB_Maintenance_M002.Maintenance[1],DB_M002_ISC_CAM_Status.DataCollection.BeltRunTime,DB_Maintenance_M002.Threshold[1],DB_M002_HMI.MaintenanceCounters.Counters[1].MaintenanceCountUntilNextMaintenance,DB_M002_HMI.MaintenanceCounters.Counters[1].WarningBit);
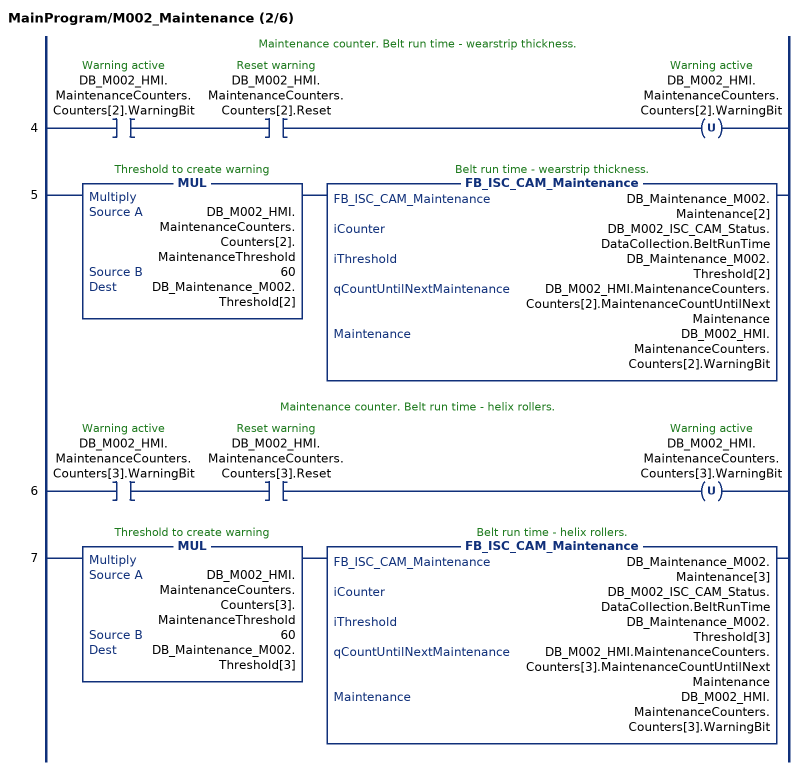
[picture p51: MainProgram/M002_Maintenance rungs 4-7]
   // Maintenance counter. Belt run time - wearstrip thickness.
   4: XIC(DB_M002_HMI.MaintenanceCounters.Counters[2].WarningBit)XIC(DB_M002_HMI.MaintenanceCounters.Counters[2].Reset)OTU(DB_M002_HMI.MaintenanceCounters.Counters[2].WarningBit);
   5: MUL(DB_M002_HMI.MaintenanceCounters.Counters[2].MaintenanceThreshold,60,DB_Maintenance_M002.Threshold[2])FB_ISC_CAM_Maintenance(DB_Maintenance_M002.Maintenance[2],DB_M002_ISC_CAM_Status.DataCollection.BeltRunTime,DB_Maintenance_M002.Threshold[2],DB_M002_HMI.MaintenanceCounters.Counters[2].MaintenanceCountUntilNextMaintenance,DB_M002_HMI.MaintenanceCounters.Counters[2].WarningBit);
   // Maintenance counter. Belt run time - helix rollers.
   6: XIC(DB_M002_HMI.MaintenanceCounters.Counters[3].WarningBit)XIC(DB_M002_HMI.MaintenanceCounters.Counters[3].Reset)OTU(DB_M002_HMI.MaintenanceCounters.Counters[3].WarningBit);
   7: MUL(DB_M002_HMI.MaintenanceCounters.Counters[3].MaintenanceThreshold,60,DB_Maintenance_M002.Threshold[3])FB_ISC_CAM_Maintenance(DB_Maintenance_M002.Maintenance[3],DB_M002_ISC_CAM_Status.DataCollection.BeltRunTime,DB_Maintenance_M002.Threshold[3],DB_M002_HMI.MaintenanceCounters.Counters[3].MaintenanceCountUntilNextMaintenance,DB_M002_HMI.MaintenanceCounters.Counters[3].WarningBit);
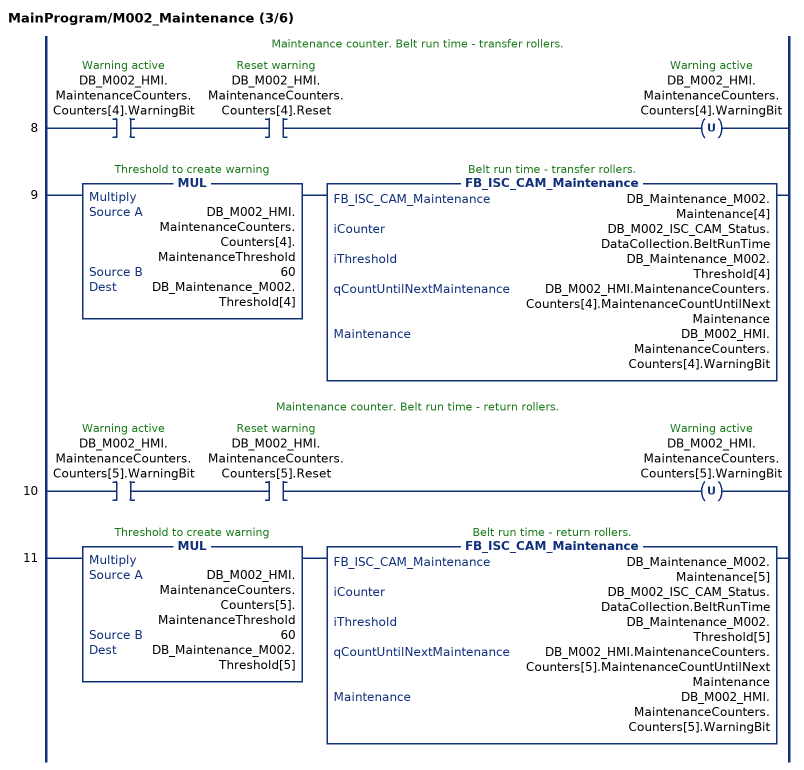
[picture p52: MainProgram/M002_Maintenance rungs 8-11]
   // Maintenance counter. Belt run time - transfer rollers.
   8: XIC(DB_M002_HMI.MaintenanceCounters.Counters[4].WarningBit)XIC(DB_M002_HMI.MaintenanceCounters.Counters[4].Reset)OTU(DB_M002_HMI.MaintenanceCounters.Counters[4].WarningBit);
   9: MUL(DB_M002_HMI.MaintenanceCounters.Counters[4].MaintenanceThreshold,60,DB_Maintenance_M002.Threshold[4])FB_ISC_CAM_Maintenance(DB_Maintenance_M002.Maintenance[4],DB_M002_ISC_CAM_Status.DataCollection.BeltRunTime,DB_Maintenance_M002.Threshold[4],DB_M002_HMI.MaintenanceCounters.Counters[4].MaintenanceCountUntilNextMaintenance,DB_M002_HMI.MaintenanceCounters.Counters[4].WarningBit);
   // Maintenance counter. Belt run time - return rollers.
   10: XIC(DB_M002_HMI.MaintenanceCounters.Counters[5].WarningBit)XIC(DB_M002_HMI.MaintenanceCounters.Counters[5].Reset)OTU(DB_M002_HMI.MaintenanceCounters.Counters[5].WarningBit);
   11: MUL(DB_M002_HMI.MaintenanceCounters.Counters[5].MaintenanceThreshold,60,DB_Maintenance_M002.Threshold[5])FB_ISC_CAM_Maintenance(DB_Maintenance_M002.Maintenance[5],DB_M002_ISC_CAM_Status.DataCollection.BeltRunTime,DB_Maintenance_M002.Threshold[5],DB_M002_HMI.MaintenanceCounters.Counters[5].MaintenanceCountUntilNextMaintenance,DB_M002_HMI.MaintenanceCounters.Counters[5].WarningBit);
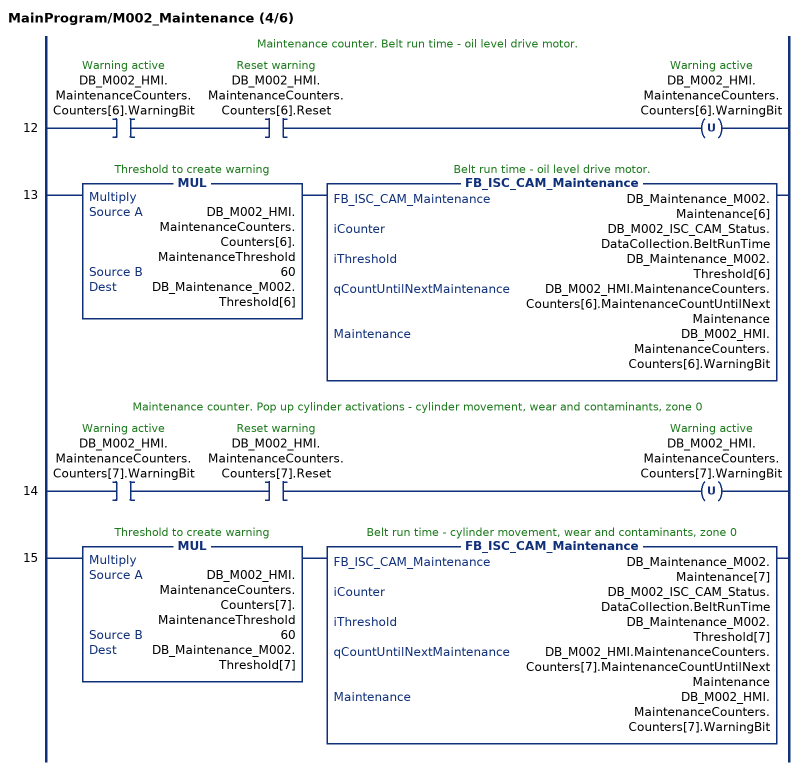
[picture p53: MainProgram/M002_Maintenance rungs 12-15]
   // Maintenance counter. Belt run time - oil level drive motor.
   12: XIC(DB_M002_HMI.MaintenanceCounters.Counters[6].WarningBit)XIC(DB_M002_HMI.MaintenanceCounters.Counters[6].Reset)OTU(DB_M002_HMI.MaintenanceCounters.Counters[6].WarningBit);
   13: MUL(DB_M002_HMI.MaintenanceCounters.Counters[6].MaintenanceThreshold,60,DB_Maintenance_M002.Threshold[6])FB_ISC_CAM_Maintenance(DB_Maintenance_M002.Maintenance[6],DB_M002_ISC_CAM_Status.DataCollection.BeltRunTime,DB_Maintenance_M002.Threshold[6],DB_M002_HMI.MaintenanceCounters.Counters[6].MaintenanceCountUntilNextMaintenance,DB_M002_HMI.MaintenanceCounters.Counters[6].WarningBit);
   // Maintenance counter. Pop up cylinder activations - cylinder movement, wear and contaminants, zone 0
   14: XIC(DB_M002_HMI.MaintenanceCounters.Counters[7].WarningBit)XIC(DB_M002_HMI.MaintenanceCounters.Counters[7].Reset)OTU(DB_M002_HMI.MaintenanceCounters.Counters[7].WarningBit);
   15: MUL(DB_M002_HMI.MaintenanceCounters.Counters[7].MaintenanceThreshold,60,DB_Maintenance_M002.Threshold[7])FB_ISC_CAM_Maintenance(DB_Maintenance_M002.Maintenance[7],DB_M002_ISC_CAM_Status.DataCollection.BeltRunTime,DB_Maintenance_M002.Threshold[7],DB_M002_HMI.MaintenanceCounters.Counters[7].MaintenanceCountUntilNextMaintenance,DB_M002_HMI.MaintenanceCounters.Counters[7].WarningBit);
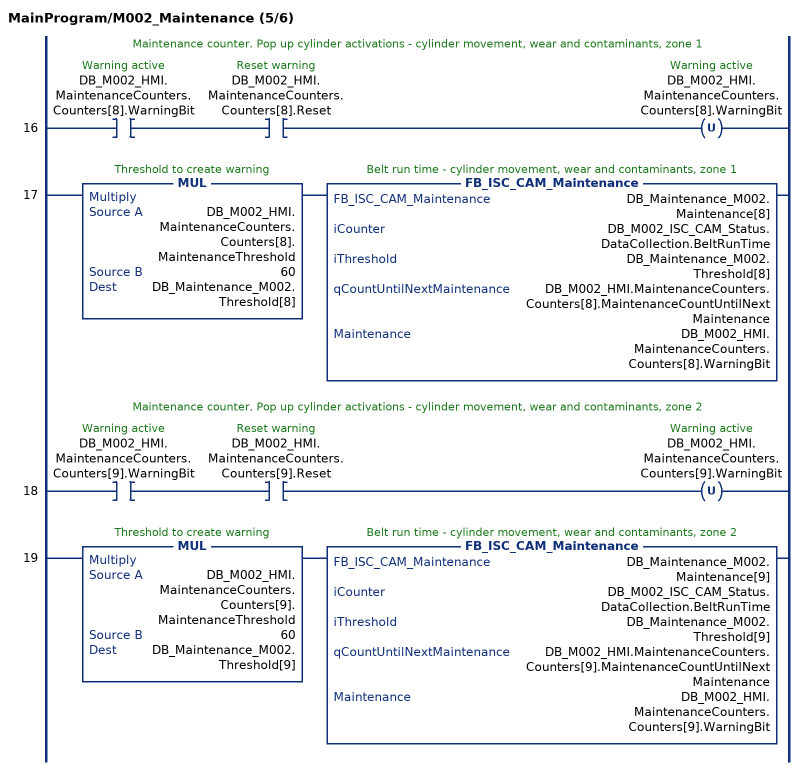
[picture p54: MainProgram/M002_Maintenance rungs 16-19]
   // Maintenance counter. Pop up cylinder activations - cylinder movement, wear and contaminants, zone 1
   16: XIC(DB_M002_HMI.MaintenanceCounters.Counters[8].WarningBit)XIC(DB_M002_HMI.MaintenanceCounters.Counters[8].Reset)OTU(DB_M002_HMI.MaintenanceCounters.Counters[8].WarningBit);
   17: MUL(DB_M002_HMI.MaintenanceCounters.Counters[8].MaintenanceThreshold,60,DB_Maintenance_M002.Threshold[8])FB_ISC_CAM_Maintenance(DB_Maintenance_M002.Maintenance[8],DB_M002_ISC_CAM_Status.DataCollection.BeltRunTime,DB_Maintenance_M002.Threshold[8],DB_M002_HMI.MaintenanceCounters.Counters[8].MaintenanceCountUntilNextMaintenance,DB_M002_HMI.MaintenanceCounters.Counters[8].WarningBit);
   // Maintenance counter. Pop up cylinder activations - cylinder movement, wear and contaminants, zone 2
   18: XIC(DB_M002_HMI.MaintenanceCounters.Counters[9].WarningBit)XIC(DB_M002_HMI.MaintenanceCounters.Counters[9].Reset)OTU(DB_M002_HMI.MaintenanceCounters.Counters[9].WarningBit);
   19: MUL(DB_M002_HMI.MaintenanceCounters.Counters[9].MaintenanceThreshold,60,DB_Maintenance_M002.Threshold[9])FB_ISC_CAM_Maintenance(DB_Maintenance_M002.Maintenance[9],DB_M002_ISC_CAM_Status.DataCollection.BeltRunTime,DB_Maintenance_M002.Threshold[9],DB_M002_HMI.MaintenanceCounters.Counters[9].MaintenanceCountUntilNextMaintenance,DB_M002_HMI.MaintenanceCounters.Counters[9].WarningBit);
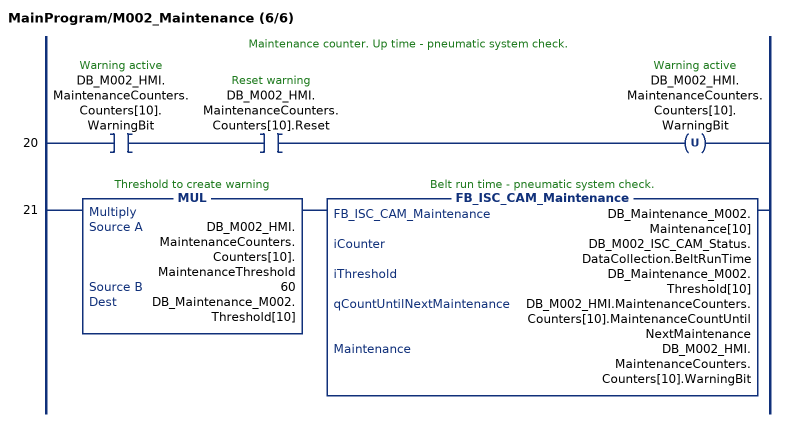
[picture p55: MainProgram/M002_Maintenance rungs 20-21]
   // Maintenance counter. Up time - pneumatic system check.
   20: XIC(DB_M002_HMI.MaintenanceCounters.Counters[10].WarningBit)XIC(DB_M002_HMI.MaintenanceCounters.Counters[10].Reset)OTU(DB_M002_HMI.MaintenanceCounters.Counters[10].WarningBit);
   21: MUL(DB_M002_HMI.MaintenanceCounters.Counters[10].MaintenanceThreshold,60,DB_Maintenance_M002.Threshold[10])FB_ISC_CAM_Maintenance(DB_Maintenance_M002.Maintenance[10],DB_M002_ISC_CAM_Status.DataCollection.BeltRunTime,DB_Maintenance_M002.Threshold[10],DB_M002_HMI.MaintenanceCounters.Counters[10].MaintenanceCountUntilNextMaintenance,DB_M002_HMI.MaintenanceCounters.Counters[10].WarningBit);
END_ROUTINE

ROUTINE Main   (* ladder *)
// General Main
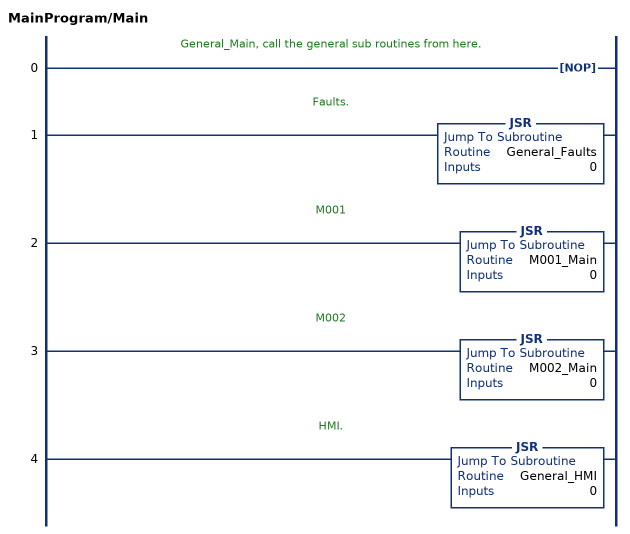
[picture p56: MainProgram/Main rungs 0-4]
   // General_Main, call the general sub routines from here.
   0: NOP();
   // Faults.
   1: JSR(General_Faults,0);
   // M001
   2: JSR(M001_Main,0);
   // M002
   3: JSR(M002_Main,0);
   // HMI.
   4: JSR(General_HMI,0);
END_ROUTINE

ROUTINE MainRoutine   (* ladder *)
// Main Program Sweep (Cycle)
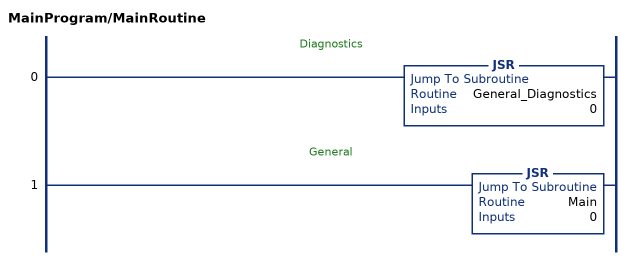
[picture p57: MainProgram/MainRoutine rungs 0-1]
   // Diagnostics
   0: JSR(General_Diagnostics,0);
   // General
   1: JSR(Main,0);
END_ROUTINE
END_PROGRAM

PROGRAM Startup   (* main routine StartupRoutine *)
// Startup

ROUTINE StartupRoutine   (* structured text *)
// Startup
   // Startup routine.
   
   // M001 Maintenance Thressholds.
   
   IF DB_M001_HMI.MaintenanceCounters.Counters[0].MaintenanceThreshold = 0 THEN
       DB_M001_HMI.MaintenanceCounters.Counters[0].MaintenanceThreshold := 8000;
   END_IF;
   
   IF DB_M001_HMI.MaintenanceCounters.Counters[1].MaintenanceThreshold = 0 THEN
       DB_M001_HMI.MaintenanceCounters.Counters[1].MaintenanceThreshold := 8000;
   END_IF;
   
   IF DB_M001_HMI.MaintenanceCounters.Counters[2].MaintenanceThreshold =0 THEN
       DB_M001_HMI.MaintenanceCounters.Counters[2].MaintenanceThreshold := 8000;
   END_IF;
   
   IF DB_M001_HMI.MaintenanceCounters.Counters[3].MaintenanceThreshold = 0 THEN
      DB_M001_HMI.MaintenanceCounters.Counters[3].MaintenanceThreshold := 8000;
   END_IF;
   
   IF DB_M001_HMI.MaintenanceCounters.Counters[4].MaintenanceThreshold = 0 THEN
      DB_M001_HMI.MaintenanceCounters.Counters[4].MaintenanceThreshold := 8000;
   END_IF;
   
   IF DB_M001_HMI.MaintenanceCounters.Counters[5].MaintenanceThreshold = 0 THEN
       DB_M001_HMI.MaintenanceCounters.Counters[5].MaintenanceThreshold := 16000;
   END_IF;
   
   IF DB_M001_HMI.MaintenanceCounters.Counters[6].MaintenanceThreshold = 0 THEN
       DB_M001_HMI.MaintenanceCounters.Counters[6].MaintenanceThreshold := 16000;
   END_IF;
   
   IF DB_M001_HMI.MaintenanceCounters.Counters[7].MaintenanceThreshold = 0 THEN
       DB_M001_HMI.MaintenanceCounters.Counters[7].MaintenanceThreshold := 8000;
   END_IF;
   
   IF DB_M001_HMI.MaintenanceCounters.Counters[8].MaintenanceThreshold = 0 THEN
       DB_M001_HMI.MaintenanceCounters.Counters[8].MaintenanceThreshold := 8000;
   END_IF;
   
   IF DB_M001_HMI.MaintenanceCounters.Counters[9].MaintenanceThreshold = 0 THEN
       DB_M001_HMI.MaintenanceCounters.Counters[9].MaintenanceThreshold := 8000;
   END_IF;
   
   IF DB_M001_HMI.MaintenanceCounters.Counters[10].MaintenanceThreshold = 0 THEN
       DB_M001_HMI.MaintenanceCounters.Counters[10].MaintenanceThreshold := 16000;
   END_IF;
   
   
   
   
   // M002 Maintenance Thressholds
   
   IF DB_M002_HMI.MaintenanceCounters.Counters[0].MaintenanceThreshold = 0 THEN
       DB_M002_HMI.MaintenanceCounters.Counters[0].MaintenanceThreshold := 8000;
   END_IF;
   
   IF DB_M002_HMI.MaintenanceCounters.Counters[1].MaintenanceThreshold = 0 THEN
       DB_M002_HMI.MaintenanceCounters.Counters[0].MaintenanceThreshold := 8000;
   END_IF;
   
   IF DB_M002_HMI.MaintenanceCounters.Counters[2].MaintenanceThreshold = 0 THEN
       DB_M002_HMI.MaintenanceCounters.Counters[2].MaintenanceThreshold := 8000;
   END_IF;
   
   IF DB_M002_HMI.MaintenanceCounters.Counters[3].MaintenanceThreshold = 0 THEN
       DB_M002_HMI.MaintenanceCounters.Counters[3].MaintenanceThreshold := 8000;
   END_IF;
   
   IF DB_M002_HMI.MaintenanceCounters.Counters[4].MaintenanceThreshold = 0 THEN
       DB_M002_HMI.MaintenanceCounters.Counters[4].MaintenanceThreshold := 8000;
   END_IF;
   
   IF DB_M002_HMI.MaintenanceCounters.Counters[5].MaintenanceThreshold = 0 THEN
       DB_M002_HMI.MaintenanceCounters.Counters[5].MaintenanceThreshold := 16000;
   END_IF;
   
   IF DB_M002_HMI.MaintenanceCounters.Counters[6].MaintenanceThreshold = 0 THEN
       DB_M002_HMI.MaintenanceCounters.Counters[6].MaintenanceThreshold := 16000;
   END_IF;
   
   IF DB_M002_HMI.MaintenanceCounters.Counters[7].MaintenanceThreshold = 0 THEN
       DB_M002_HMI.MaintenanceCounters.Counters[7].MaintenanceThreshold := 8000;
   END_IF;
   
   IF DB_M002_HMI.MaintenanceCounters.Counters[8].MaintenanceThreshold = 0 THEN
       DB_M002_HMI.MaintenanceCounters.Counters[8].MaintenanceThreshold := 8000;
   END_IF;
   
   IF DB_M002_HMI.MaintenanceCounters.Counters[9].MaintenanceThreshold = 0 THEN
       DB_M002_HMI.MaintenanceCounters.Counters[9].MaintenanceThreshold := 8000;
   END_IF;
   
   IF DB_M002_HMI.MaintenanceCounters.Counters[10].MaintenanceThreshold = 0 THEN
       DB_M002_HMI.MaintenanceCounters.Counters[10].MaintenanceThreshold := 16000;
   END_IF;
   
   
   
   
END_ROUTINE
END_PROGRAM
